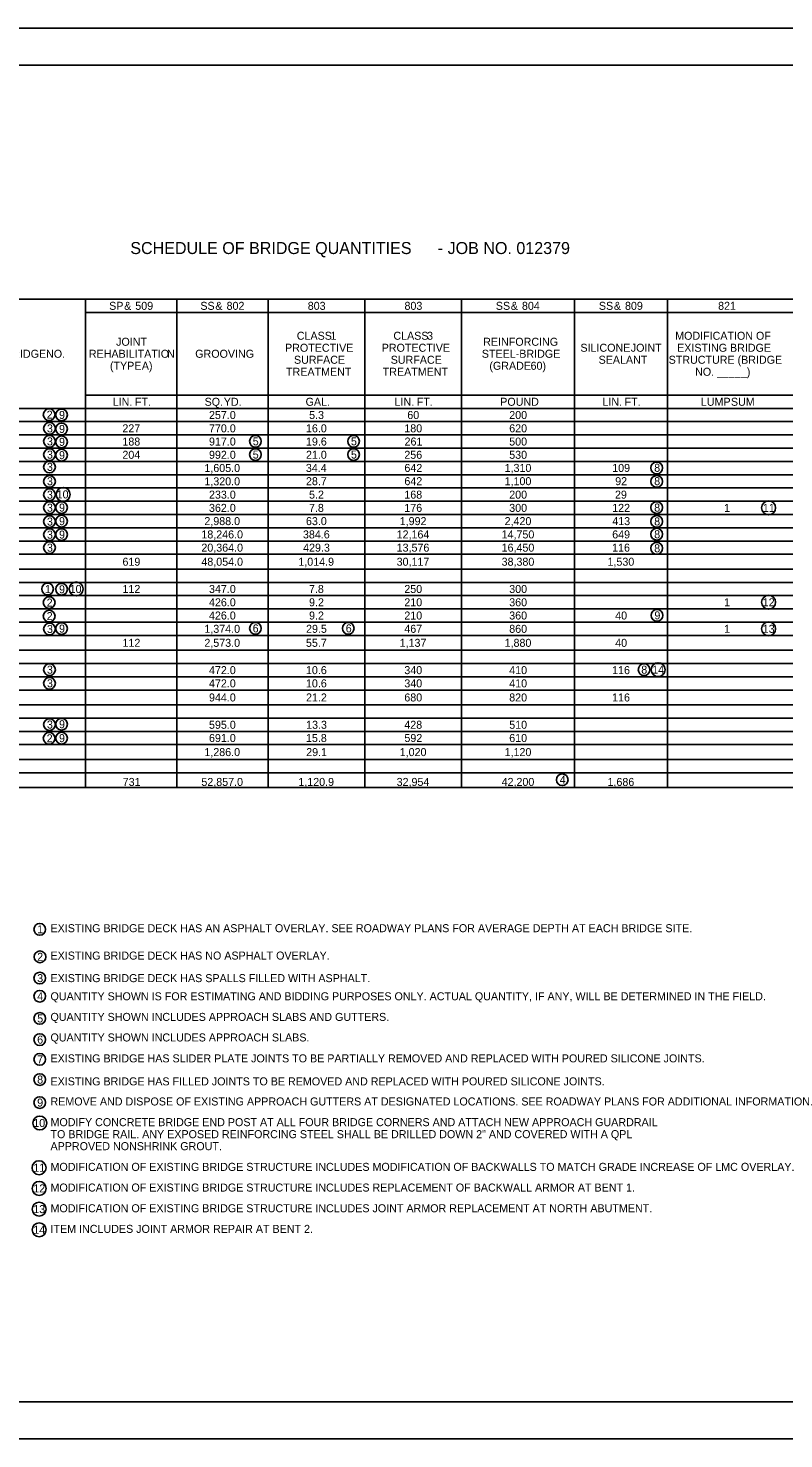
# Model space of a CAD drawing. Extents: x 16 to 1228740, y 11 to 152440.
# Drawn here: x 16.632 to 17.615, y 10.709 to 12.543 of the extents above; entities that cross this region are included whole.
import ezdxf

# ---------------------------------------------------------------- set-up
doc = ezdxf.new("R2010")
doc.units = 0
doc.layers.add('B_Text', color=7, linetype='Continuous')
doc.layers.add('R_Border', color=7, linetype='Continuous')

msp = doc.modelspace()

# ---------------------------------------------------------------- linework, layer by layer
at = {"layer": 'B_Text'}
for p, q in [((15.9076, 12.1907), (18.2926, 12.1907)), ((16.7067, 11.5559), (16.7067, 12.1907)), ((16.7067, 12.1734), (18.2926, 12.1734)), ((16.8253, 11.5559), (16.8253, 12.1907)), ((16.944, 11.5559), (16.944, 12.1907)), ((17.0697, 11.5559), (17.0697, 12.1907)), ((17.1954, 11.5559), (17.1954, 12.1907)), ((17.3425, 11.5559), (17.3425, 12.1907)), ((17.4631, 11.5559), (17.4631, 12.1907)), ((16.7067, 12.0659), (18.2926, 12.0659)), ((15.9076, 12.0487), (18.2926, 12.0487)), ((16.009, 12.0315), (18.2926, 12.0315)), ((16.009, 12.0142), (18.2926, 12.0142)), ((16.009, 11.997), (18.2926, 11.997)), ((16.009, 11.9797), (18.2926, 11.9797)), ((16.009, 11.9625), (18.2926, 11.9625)), ((16.009, 11.9453), (18.2926, 11.9453)), ((16.009, 11.928), (18.2926, 11.928)), ((16.009, 11.9108), (18.2926, 11.9108)), ((16.009, 11.8935), (18.2926, 11.8935)), ((16.009, 11.8763), (18.2926, 11.8763)), ((16.009, 11.8591), (18.2926, 11.8591)), ((15.9076, 11.8398), (18.2926, 11.8398)), ((15.9076, 11.8226), (18.2926, 11.8226)), ((16.009, 11.8053), (18.2926, 11.8053)), ((16.009, 11.7881), (18.2926, 11.7881)), ((16.009, 11.7709), (18.2926, 11.7709)), ((16.009, 11.7536), (18.2926, 11.7536)), ((15.9076, 11.7344), (18.2926, 11.7344)), ((15.9076, 11.7171), (18.2926, 11.7171)), ((16.009, 11.6999), (18.2926, 11.6999)), ((16.009, 11.6826), (18.2926, 11.6826)), ((15.9076, 11.6634), (18.2926, 11.6634)), ((15.9076, 11.6461), (18.2926, 11.6461)), ((16.009, 11.6289), (18.2926, 11.6289)), ((16.009, 11.6117), (18.2926, 11.6117)), ((15.9076, 11.5924), (18.2926, 11.5924)), ((15.9076, 11.5752), (18.2926, 11.5752)), ((15.9076, 11.5559), (18.2926, 11.5559))]:
    msp.add_line(p, q, dxfattribs=at)
for centre, radius in [((16.6593, 12.0405), 0.00762), ((16.6754, 12.0402), 0.00762), ((16.6597, 12.0227), 0.00762), ((16.6754, 12.022), 0.00762), ((16.6597, 12.0059), 0.00762), ((16.6754, 12.0052), 0.00762), ((16.9275, 12.0059), 0.00762), ((17.0551, 12.0059), 0.00762), ((16.6597, 11.9886), 0.00762), ((16.6754, 11.9879), 0.00762), ((16.9275, 11.9887), 0.00762), ((17.0551, 11.9887), 0.00762), ((16.6597, 11.9725), 0.00762), ((17.4493, 11.9713), 0.00762), ((16.6597, 11.9538), 0.00762), ((17.4493, 11.9538), 0.00762), ((16.6597, 11.9365), 0.00762), ((16.6775, 11.9369), 0.00906), ((16.6597, 11.9197), 0.00762), ((16.6754, 11.9198), 0.00762), ((17.4493, 11.9198), 0.00762), ((17.5948, 11.9194), 0.00906), ((16.6597, 11.9016), 0.00762), ((16.6754, 11.9021), 0.00762), ((17.4493, 11.9018), 0.00762), ((16.6597, 11.8846), 0.00762), ((16.6754, 11.8847), 0.00762), ((17.4493, 11.8852), 0.00762), ((16.6597, 11.8677), 0.00762), ((17.4493, 11.8669), 0.00762), ((16.6572, 11.814), 0.00762), ((16.6754, 11.8137), 0.00762), ((16.6944, 11.814), 0.00906), ((16.6593, 11.7963), 0.00762), ((17.5948, 11.7967), 0.00906), ((16.6593, 11.7787), 0.00762), ((16.6754, 11.7625), 0.00762), ((16.9275, 11.7628), 0.00762), ((17.0482, 11.7628), 0.00762), ((17.4496, 11.7797), 0.00762), ((17.5948, 11.7622), 0.00906), ((16.6597, 11.762), 0.00762), ((16.6597, 11.7091), 0.00762), ((17.4329, 11.7091), 0.00762), ((17.4511, 11.7091), 0.00906), ((16.6597, 11.6914), 0.00762), ((16.6597, 11.6378), 0.00762), ((16.6754, 11.6382), 0.00762), ((16.6593, 11.6199), 0.00762), ((16.6754, 11.6201), 0.00762), ((17.3264, 11.566), 0.00762), ((16.6471, 11.3716), 0.00762), ((16.6473, 11.3359), 0.00762), ((16.6471, 11.3082), 0.00762), ((16.6471, 11.2847), 0.00762), ((16.6471, 11.2558), 0.00762), ((16.6471, 11.2283), 0.00762), ((16.6471, 11.2026), 0.00762), ((16.6471, 11.1764), 0.00762), ((16.6471, 11.1465), 0.00762), ((16.6471, 11.1199), 0.00906), ((16.6461, 11.0618), 0.00906), ((16.6463, 11.0349), 0.00906), ((16.6462, 11.008), 0.00906), ((16.6462, 10.9811), 0.00906)]:
    msp.add_circle(centre, radius, dxfattribs=at)
at = {"layer": 'R_Border'}
for p, q in [((15.7833, 12.4948), (18.4422, 12.4948)), ((18.4422, 10.7576), (15.7833, 10.7576))]:
    msp.add_line(p, q, dxfattribs=at)
msp.add_lwpolyline([(15.6569, 12.5428), (18.4903, 12.5428), (18.4903, 10.7095), (15.6569, 10.7095)], close=True, dxfattribs=at)

# ---------------------------------------------------------------- texts
at = {"layer": 'B_Text'}
for s, height, p in [('SCHEDULE OF BRIDGE QUANTITIES', 0.015625, (16.7648, 12.2493)), (' - JOB NO. 012379', 0.015625, (17.1588, 12.2493)), ('SP', 0.0104, (16.7373, 12.1768)), (' &', 0.0104, (16.7529, 12.1768)), (' 509', 0.0104, (16.7674, 12.1768)), ('SS', 0.0104, (16.8559, 12.1768)), (' &', 0.0104, (16.8715, 12.1768)), (' 802', 0.0104, (16.8861, 12.1768)), ('803', 0.0104, (16.9955, 12.1768)), ('803', 0.0104, (17.1213, 12.1768)), ('SS', 0.0104, (17.2401, 12.1768)), (' &', 0.0104, (17.2557, 12.1768)), (' 804', 0.0104, (17.2702, 12.1768)), ('SS', 0.0104, (17.3741, 12.1768)), (' &', 0.0104, (17.3897, 12.1768)), (' 809', 0.0104, (17.4042, 12.1768)), ('821', 0.0104, (17.5291, 12.1768)), ('JOINT', 0.0104, (16.7463, 12.1301)), ('CLASS', 0.0104, (16.9813, 12.1379)), (' 1', 0.0104, (17.0212, 12.1379)), ('CLASS', 0.0104, (17.1069, 12.1379)), (' 3', 0.0104, (17.1468, 12.1379)), ('REINFORCING', 0.0104, (17.2237, 12.1301)), ('MODIFICATION OF ', 0.0104, (17.4733, 12.1379)), ('BRIDGE', 0.0104, (16.602, 12.1145)), (' NO.', 0.0104, (16.6514, 12.1145)), ('REHABILITATIO', 0.0104, (16.7109, 12.1145)), ('N', 0.0104, (16.8126, 12.1145)), ('GROOVING', 0.0104, (16.8492, 12.1145)), ('PROTECTIVE', 0.0104, (16.966, 12.1223)), ('PROTECTIVE', 0.0104, (17.0917, 12.1223)), ('STEEL-BRIDGE', 0.0104, (17.2219, 12.1145)), ('SILICONE', 0.0104, (17.3501, 12.1223)), (' JOINT', 0.0104, (17.4117, 12.1223)), ('EXISTING BRIDGE ', 0.0104, (17.4758, 12.1223)), ('(TYPE', 0.0104, (16.7383, 12.0989)), (' A)', 0.0104, (16.7759, 12.0989)), ('TREATMENT', 0.0104, (16.9673, 12.0911)), ('SURFACE', 0.0104, (16.9776, 12.1067)), ('TREATMENT', 0.0104, (17.093, 12.0911)), ('SURFACE', 0.0104, (17.1034, 12.1067)), ('(GRADE', 0.0104, (17.2317, 12.0989)), (' 60)', 0.0104, (17.2814, 12.0989)), ('SEALANT', 0.0104, (17.3737, 12.1067)), ('STRUCTURE (BRIDGE ', 0.0104, (17.4648, 12.1067)), ('NO. _____)', 0.0104, (17.4992, 12.0911)), ('2', 0.0104, (16.656, 12.0353)), ('9', 0.0104, (16.6721, 12.035)), ('LIN.', 0.0104, (16.7419, 12.0521)), (' FT.', 0.0104, (16.7669, 12.0521)), ('SQ.', 0.0104, (16.8614, 12.0521)), ('257.0', 0.0104, (16.8671, 12.0349)), (' YD.', 0.0104, (16.8825, 12.0521)), ('GAL.', 0.0104, (16.9927, 12.0521)), ('5.3', 0.0104, (16.9973, 12.0349)), ('LIN.', 0.0104, (17.1084, 12.0521)), ('60', 0.0104, (17.125, 12.0349)), (' FT.', 0.0104, (17.1334, 12.0521)), ('POUND', 0.0104, (17.2458, 12.0521)), ('200', 0.0104, (17.2575, 12.0349)), ('LIN.', 0.0104, (17.3787, 12.0521)), (' FT.', 0.0104, (17.4036, 12.0521)), ('LUMP', 0.0104, (17.5067, 12.0521)), (' SUM', 0.0104, (17.5419, 12.0521)), ('3', 0.0104, (16.6564, 12.0175)), ('9', 0.0104, (16.6721, 12.0168)), ('227', 0.0104, (16.7545, 12.0176)), ('770.0', 0.0104, (16.8671, 12.0176)), ('16.0', 0.0104, (16.9932, 12.0176)), ('180', 0.0104, (17.1211, 12.0176)), ('620', 0.0104, (17.2575, 12.0176)), ('3', 0.0104, (16.6564, 12.0006)), ('9', 0.0104, (16.6721, 12)), ('188', 0.0104, (16.7545, 12.0004)), ('917.0', 0.0104, (16.8671, 12.0004)), ('5', 0.0104, (16.924, 12.0007)), ('19.6', 0.0104, (16.9932, 12.0004)), ('5', 0.0104, (17.0517, 12.0007)), ('261', 0.0104, (17.1214, 12.0004)), ('500', 0.0104, (17.2575, 12.0004)), ('3', 0.0104, (16.6564, 11.9834)), ('9', 0.0104, (16.6721, 11.9827)), ('204', 0.0104, (16.7545, 11.9832)), ('992.0', 0.0104, (16.8671, 11.9832)), ('5', 0.0104, (16.924, 11.9835)), ('21.0', 0.0104, (16.9932, 11.9832)), ('5', 0.0104, (17.0517, 11.9835)), ('256', 0.0104, (17.1211, 11.9832)), ('530', 0.0104, (17.2575, 11.9832)), ('3', 0.0104, (16.6564, 11.9675)), ('1,605.0', 0.0104, (16.8611, 11.966)), ('34.4', 0.0104, (16.9931, 11.9661)), ('642', 0.0104, (17.1212, 11.9661)), ('1,310', 0.0104, (17.2515, 11.9661)), ('109', 0.0104, (17.3914, 11.9661)), ('8', 0.0104, (17.446, 11.9663)), ('3', 0.0104, (16.6564, 11.9488)), ('1,320.0', 0.0104, (16.8611, 11.9487)), ('28.7', 0.0104, (16.9932, 11.9489)), ('642', 0.0104, (17.1212, 11.9489)), ('1,100', 0.0104, (17.2515, 11.9489)), ('92', 0.0104, (17.3953, 11.9489)), ('8', 0.0104, (17.446, 11.9489)), ('3', 0.0104, (16.6564, 11.9313)), ('10', 0.01042, (16.669, 11.9317)), ('233.0', 0.0104, (16.8671, 11.9314)), ('5.2', 0.0104, (16.9972, 11.9314)), ('168', 0.0104, (17.1211, 11.9314)), ('200', 0.0104, (17.2575, 11.9314)), ('29', 0.01042, (17.395, 11.9314)), ('3', 0.0104, (16.6564, 11.9144)), ('9', 0.0104, (16.6721, 11.9146)), ('362.0', 0.0104, (16.8671, 11.9142)), ('7.8', 0.0104, (16.9971, 11.9142)), ('176', 0.0104, (17.1211, 11.9142)), ('300', 0.0104, (17.2575, 11.9142)), ('122', 0.0104, (17.3914, 11.9142)), ('8', 0.0104, (17.446, 11.9146)), ('1', 0.0104, (17.5369, 11.9142)), ('11', 0.01042, (17.5873, 11.9142)), ('3', 0.0104, (16.6564, 11.8964)), ('9', 0.0104, (16.6721, 11.8969)), ('2,988.0', 0.0104, (16.8611, 11.897)), ('63.0', 0.0104, (16.9932, 11.897)), ('1,992', 0.0104, (17.1151, 11.897)), ('2,420', 0.0104, (17.2515, 11.897)), ('413', 0.0104, (17.3915, 11.897)), ('8', 0.0104, (17.446, 11.8966)), ('3', 0.0104, (16.6564, 11.8794)), ('9', 0.0104, (16.6721, 11.8795)), ('18,246.0', 0.0104, (16.8572, 11.8797)), ('384.6', 0.0104, (16.9893, 11.8797)), ('12,164', 0.0104, (17.1111, 11.8797)), ('14,750', 0.0104, (17.2476, 11.8797)), ('649', 0.0104, (17.3914, 11.8797)), ('8', 0.0104, (17.446, 11.8799)), ('3', 0.0104, (16.6564, 11.8625)), ('20,364.0', 0.0104, (16.8572, 11.8625)), ('429.3', 0.0104, (16.9895, 11.8625)), ('13,576', 0.0104, (17.1111, 11.8625)), ('16,450', 0.0104, (17.2476, 11.8625)), ('116', 0.0104, (17.3913, 11.8625)), ('8', 0.0104, (17.446, 11.8617)), ('619', 0.0104, (16.7546, 11.8442)), ('48,054.0', 0.0104, (16.8572, 11.8442)), ('1,014.9', 0.0104, (16.9833, 11.8442)), ('30,117', 0.0104, (17.1111, 11.8442)), ('38,380', 0.0104, (17.2476, 11.8442)), ('1,530', 0.0104, (17.3853, 11.8442)), ('1', 0.0104, (16.6538, 11.8087)), ('9', 0.0104, (16.6721, 11.8084)), ('10', 0.01042, (16.6859, 11.8088)), ('112', 0.0104, (16.7546, 11.8088)), ('347.0', 0.0104, (16.8671, 11.8088)), ('7.8', 0.0104, (16.9971, 11.8088)), ('250', 0.0104, (17.1211, 11.8088)), ('300', 0.0104, (17.2575, 11.8088)), ('2', 0.0104, (16.656, 11.7911)), ('426.0', 0.0104, (16.8671, 11.7915)), ('9.2', 0.0104, (16.9972, 11.7915)), ('210', 0.0104, (17.1211, 11.7915)), ('360', 0.0104, (17.2575, 11.7915)), ('1', 0.0104, (17.5369, 11.7915)), ('12', 0.01042, (17.5871, 11.7915)), ('2', 0.0104, (16.656, 11.7735)), ('426.0', 0.0104, (16.8671, 11.7743)), ('9.2', 0.0104, (16.9972, 11.7743)), ('210', 0.0104, (17.1211, 11.7743)), ('360', 0.0104, (17.2575, 11.7743)), ('40', 0.0104, (17.3953, 11.7743)), ('9', 0.0104, (17.4463, 11.7745)), ('3', 0.0104, (16.6564, 11.7568)), ('9', 0.0104, (16.6721, 11.7573)), ('1,374.0', 0.0104, (16.8611, 11.757)), ('6', 0.0104, (16.9239, 11.7576)), ('29.5', 0.0104, (16.9933, 11.757)), ('6', 0.0104, (17.0449, 11.7576)), ('467', 0.0104, (17.1211, 11.757)), ('860', 0.0104, (17.2575, 11.757)), ('1', 0.0104, (17.5369, 11.757)), ('13', 0.01042, (17.5871, 11.757)), ('112', 0.0104, (16.7546, 11.7388)), ('2,573.0', 0.0104, (16.8611, 11.7388)), ('55.7', 0.0104, (16.9932, 11.7388)), ('1,137', 0.0104, (17.115, 11.7388)), ('1,880', 0.0104, (17.2515, 11.7388)), ('40', 0.0104, (17.3953, 11.7388)), ('3', 0.0104, (16.6564, 11.7039)), ('3', 0.0104, (16.6564, 11.6862)), ('472.0', 0.0104, (16.8671, 11.7033)), ('10.6', 0.0104, (16.9932, 11.7033)), ('340', 0.0104, (17.1211, 11.7033)), ('410', 0.0104, (17.2575, 11.7033)), ('116', 0.0104, (17.3913, 11.7033)), ('8', 0.0104, (17.4292, 11.7039)), ('14', 0.01042, (17.4434, 11.7039)), ('472.0', 0.0104, (16.8671, 11.6861)), ('944.0', 0.0104, (16.8671, 11.6678)), ('21.2', 0.0104, (16.9933, 11.6678)), ('10.6', 0.0104, (16.9932, 11.6861)), ('340', 0.0104, (17.1211, 11.6861)), ('680', 0.0104, (17.1211, 11.6678)), ('410', 0.0104, (17.2575, 11.6861)), ('820', 0.0104, (17.2575, 11.6678)), ('116', 0.0104, (17.3913, 11.6678)), ('3', 0.0104, (16.6564, 11.6326)), ('9', 0.0104, (16.6721, 11.633)), ('595.0', 0.0104, (16.8671, 11.6323)), ('13.3', 0.0104, (16.9934, 11.6323)), ('428', 0.0104, (17.1211, 11.6323)), ('510', 0.0104, (17.2575, 11.6323)), ('2', 0.0104, (16.656, 11.6147)), ('9', 0.0104, (16.6721, 11.6149)), ('691.0', 0.0104, (16.8671, 11.6151)), ('15.8', 0.0104, (16.9932, 11.6151)), ('592', 0.0104, (17.1212, 11.6151)), ('610', 0.0104, (17.2575, 11.6151)), ('1,286.0', 0.0104, (16.8611, 11.5968)), ('29.1', 0.0104, (16.9935, 11.5968)), ('1,020', 0.0104, (17.1151, 11.5968)), ('1,120', 0.0104, (17.2515, 11.5968)), ('731', 0.0104, (16.7549, 11.558)), ('52,857.0', 0.0104, (16.8572, 11.558)), ('1,120.9', 0.0104, (16.9833, 11.558)), ('32,954', 0.0104, (17.1111, 11.558)), ('42,200', 0.0104, (17.2476, 11.558)), ('4', 0.0104, (17.3231, 11.5608)), ('1,686', 0.0104, (17.3853, 11.558)), ('1', 0.0104, (16.6437, 11.3664)), ('EXISTING BRIDGE DECK HAS AN ASPHALT OVERLAY. SEE ROADWAY PLANS FOR AVERAGE DEPTH AT EACH BRIDGE SITE.', 0.0104167, (16.661, 11.3679)), ('2', 0.0104, (16.6437, 11.3307)), ('EXISTING BRIDGE DECK HAS NO ASPHALT OVERLAY.', 0.010417, (16.661, 11.3323)), ('3', 0.0104, (16.6437, 11.303)), ('EXISTING BRIDGE DECK HAS SPALLS FILLED WITH ASPHALT.', 0.010417, (16.661, 11.303)), ('4', 0.0104, (16.6437, 11.2795)), ('QUANTITY SHOWN IS FOR ESTIMATING AND BIDDING PURPOSES ONLY. ACTUAL QUANTITY, IF ANY, WILL BE DETERMINED IN THE FIELD.', 0.0104167, (16.661, 11.2794)), ('5', 0.0104, (16.6437, 11.2506)), ('QUANTITY SHOWN INCLUDES APPROACH SLABS AND GUTTERS.', 0.010417, (16.661, 11.2526)), ('6', 0.0104, (16.6437, 11.2231)), ('QUANTITY SHOWN INCLUDES APPROACH SLABS.', 0.010417, (16.661, 11.2259)), ('7', 0.0104, (16.6437, 11.1974)), ('EXISTING BRIDGE HAS SLIDER PLATE JOINTS TO BE PARTIALLY REMOVED AND REPLACED WITH POURED SILICONE JOINTS.', 0.0104167, (16.661, 11.1987)), ('8', 0.0104, (16.6437, 11.1712)), ('EXISTING BRIDGE HAS FILLED JOINTS TO BE REMOVED AND REPLACED WITH POURED SILICONE JOINTS.', 0.010417, (16.661, 11.1688)), ('9', 0.0104, (16.6437, 11.1413)), ('REMOVE AND DISPOSE OF EXISTING APPROACH GUTTERS AT DESIGNATED LOCATIONS. SEE ROADWAY PLANS FOR ADDITIONAL INFORMATION.', 0.0104167, (16.661, 11.1427)), ('10', 0.01042, (16.6386, 11.1147)), ('TO BRIDGE RAIL. ANY EXPOSED REINFORCING STEEL SHALL BE DRILLED DOWN 2" AND COVERED WITH A QPL ', 0.010417, (16.661, 11.1002)), ('MODIFY CONCRETE BRIDGE END POST AT ALL FOUR BRIDGE CORNERS AND ATTACH NEW APPROACH GUARDRAIL ', 0.010417, (16.661, 11.1158)), ('APPROVED NONSHRINK GROUT.', 0.010417, (16.661, 11.0846)), ('11', 0.01042, (16.6386, 11.0566)), ('MODIFICATION OF EXISTING BRIDGE STRUCTURE INCLUDES MODIFICATION OF BACKWALLS TO MATCH GRADE INCREASE OF LMC OVERLAY.', 0.0104167, (16.661, 11.0577)), ('12', 0.01042, (16.6386, 11.0297)), ('MODIFICATION OF EXISTING BRIDGE STRUCTURE INCLUDES REPLACEMENT OF BACKWALL ARMOR AT BENT 1.', 0.010417, (16.661, 11.0308)), ('13', 0.01042, (16.6386, 11.0028)), ('MODIFICATION OF EXISTING BRIDGE STRUCTURE INCLUDES JOINT ARMOR REPLACEMENT AT NORTH ABUTMENT.', 0.010417, (16.661, 11.0039)), ('14', 0.01042, (16.6386, 10.9759)), ('ITEM INCLUDES JOINT ARMOR REPAIR AT BENT 2.', 0.010417, (16.661, 10.9771))]:
    msp.add_text(s, height=height, dxfattribs=at).set_placement(p)

doc.saveas('drawing.dxf')
